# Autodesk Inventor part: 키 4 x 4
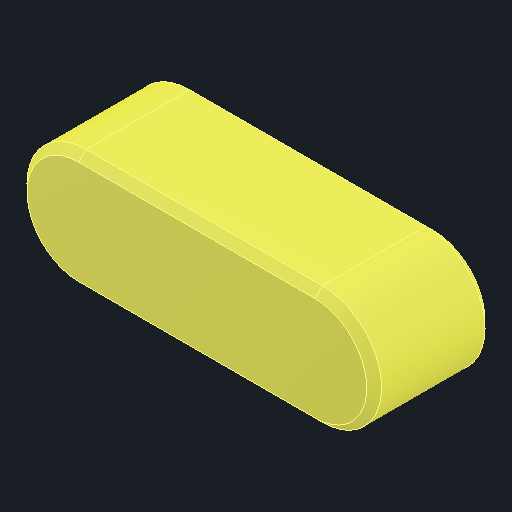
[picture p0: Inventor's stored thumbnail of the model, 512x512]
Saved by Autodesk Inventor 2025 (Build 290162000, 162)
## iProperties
Created: 2025-08
Part Number: 키 4 x 4
Material: 강철, 연강
Description: 키 및 해당 키홈
Document SubType Name: Modeling
Designer: infra023
Density: 7.86 g/cm^3
Appearance: 기본값
Author: jhkim
Sending System: Autodesk Inventor 2026
Preprocessor: ST-DEVELOPER v20.1
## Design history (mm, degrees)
feature "Solid1"
node "솔리드1"
